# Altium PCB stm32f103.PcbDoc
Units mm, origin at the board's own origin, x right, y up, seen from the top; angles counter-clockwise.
Board outline 152.4 x 101.6 mm, 2 copper layers (Top Layer, Bottom Layer); 61 components, 40 nets, 251 pads, 92 vias.
Unrouted connection lines stored in the file: 1.
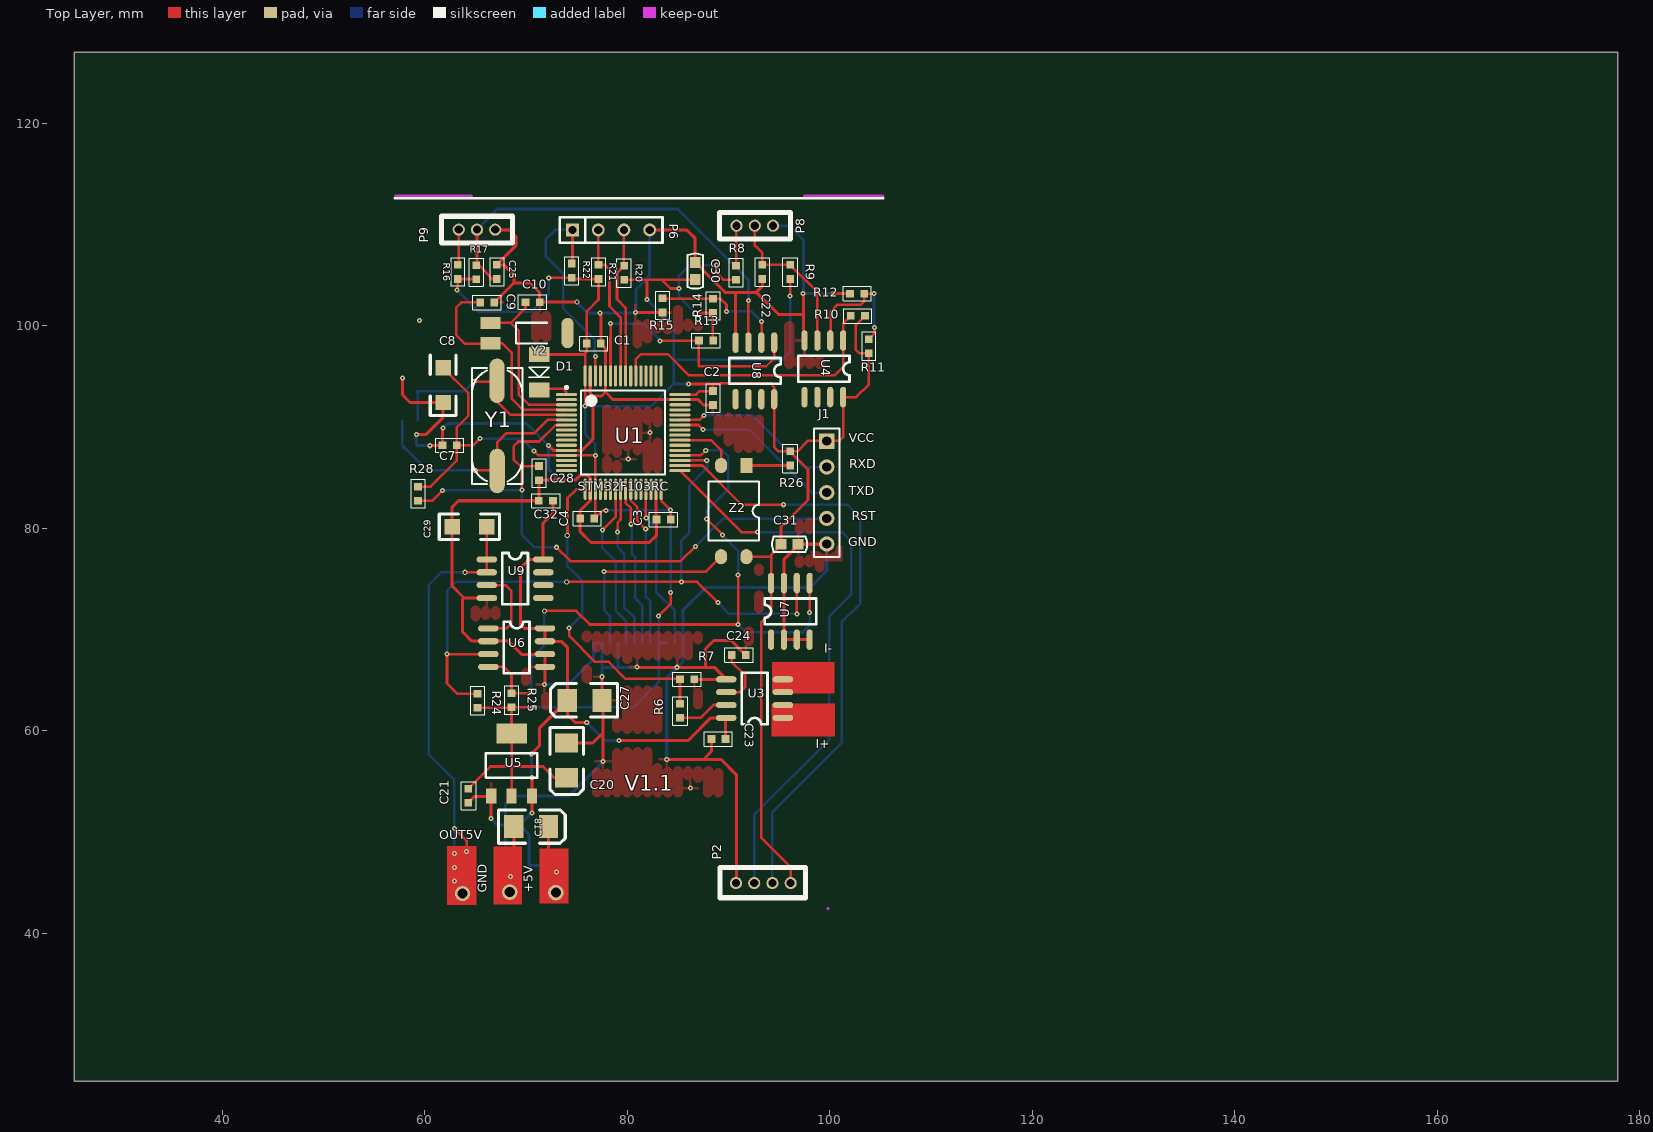
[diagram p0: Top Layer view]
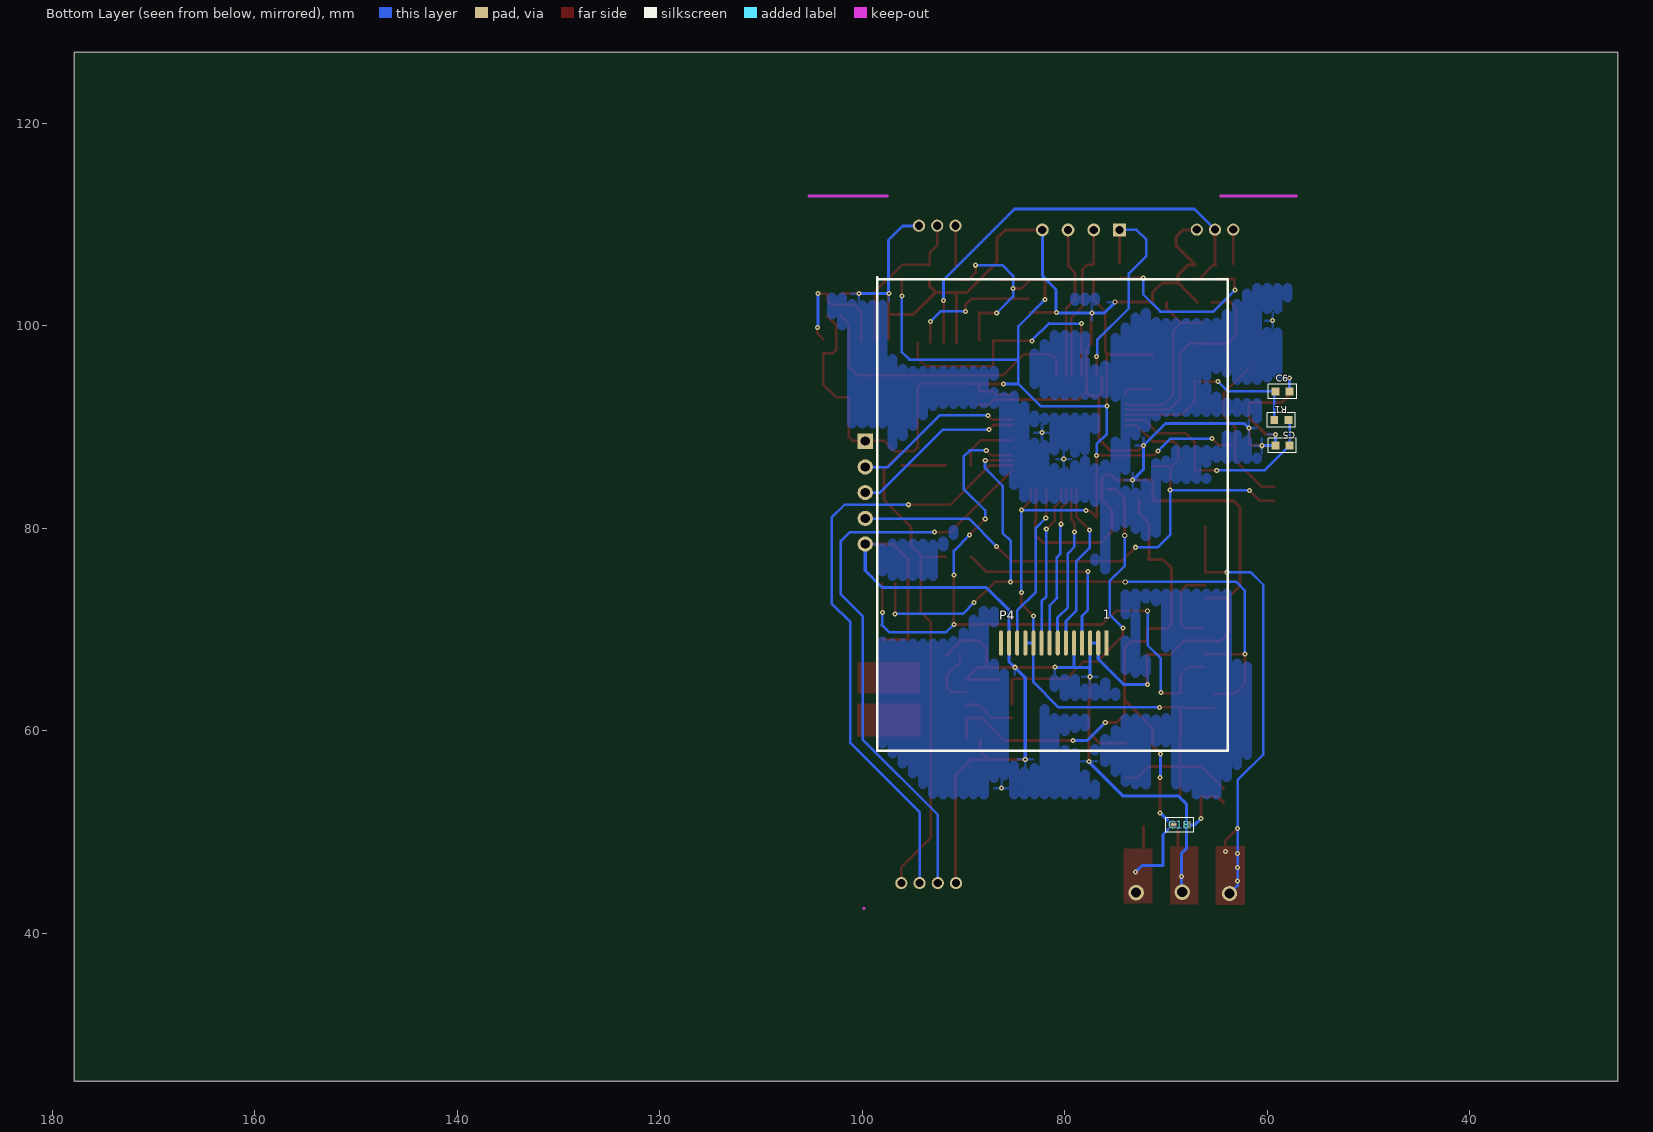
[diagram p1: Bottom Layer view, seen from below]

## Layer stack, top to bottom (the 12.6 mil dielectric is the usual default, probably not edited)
Top Layer: signal copper 0.0356
Dielectric: dielectric 0.32, FR-4, Dk 4.8
Bottom Layer: signal copper 0.0356

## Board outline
25.4,25.4 177.8,25.4 177.8,127 25.4,127

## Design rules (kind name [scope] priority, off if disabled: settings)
Clearance [All] p1: gap=0.5
PlaneClearance [All] p1: clearance=0.8
PolygonConnect [All] p1: connectstyle=Relief reliefconductorwidth=0.254 reliefentries=4 polygonreliefangle="90 Angle"
RoutingVias [All] p1: holewidth=0.2 width=0.5 viastyle="Through Hole" minholewidth=0.2 minwidth=0.5 maxholewidth=0.2 maxwidth=0.5
SMDToCorner [All] p1: distance=0
SMDToPlane [All] p1: distance=0
SilkscreenOverComponentPads [IsPad] p1: minsilkscreentomaskgap=0.254
SolderMaskExpansion [All] p1: expansion=0.5
TestPointUsage [All] p1: valid=0 allowmultiple=FALSE
Testpoint [(IsPad And (OnTopLayer Or OnBottomLayer))] p1: side=3 testpointundercomponent=TRUE minsize=1.016 maxsize=2.54 preferedsize=1.524 minholesize=0 maxholesize=1.016 preferedholesize=0.813 testpointgrid=0.025 style=297 order=0-112345678
Width GND [InNet('BOOT0')] p1: maxlimit=0.5 minlimit=0.254 preferedwidth=0.254 toplayer_minwidth=0.3 toplayer_prefwidth=0.5 bottomlayer_minwidth=0.3 bottomlayer_prefwidth=0.5 minimp=50.000000 maximp=50.000000 favimp=50.000000
Width VCC5 [InNet('VCC5')] p2: maxlimit=0.5 minlimit=0.254 preferedwidth=0.254 toplayer_minwidth=0.3 toplayer_prefwidth=0.5 bottomlayer_minwidth=0.3 bottomlayer_prefwidth=0.5 minimp=50.000000 maximp=50.000000 favimp=50.000000
Width [All] p3: maxlimit=0.3 minlimit=0.254 preferedwidth=0.254 toplayer_prefwidth=0.3 bottomlayer_prefwidth=0.3 minimp=50.000000 maximp=50.000000 favimp=50.000000
22 further rules are at their usual default settings.

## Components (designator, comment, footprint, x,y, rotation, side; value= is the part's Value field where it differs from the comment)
C1 "Cap" 0603 76,98.236 r0 top
C2 "Cap" 0603 88.462,93.563 r270 top
C3 "Cap" 0603 82.899,80.863 r0 top
C4 "Cap" 0603 75.355,80.964 r0 top
C5 "Cap" 0603 59.201,88.178 r180 bottom
C6 "Cap" 0603 57.804,93.512 r0 bottom
C7 "Cap" 0603 63.163,88.203 r180 top
C8 "Cap" 1206_C 61.817,92.42 r90 top
C9 "Cap" 0603 65.475,102.3 r0 top
C10 "Cap" 0603 69.95,102.325 r0 top
C18 "Cap" 0603 67.964,50.713 r0 bottom
C20 "10u" 3528#1 74.009,55.361 r270 top
C21 "0.1u" 0603 64.306,52.897 r90 top
C22 "104" 0603 93.338,104.612 r90 top
C23 "Cap" 0603 88.309,59.196 r0 top
C24 "Cap" 0603 91.713,67.477 r180 top
C25 "104" 0603 67.125,106.009 r270 top
C27 "10u" 3528#1 74.085,63.006 r180 top
C28 "0.1uF" 0603 72.663,82.717 r180 top
C29 "47u" 1206 66.135,80.151 r180 top
C30 "Cap" C-RAD-0603 86.709,105.399 r270 top
C31 "Cap" C-RAD-0603 96.025,78.425 r0 top
C32 "Cap" 0603 71.291,86.146 r270 top
D1 "Diode" DIODE-1206 71.304,97.16 r270 top
J1 "Header 5" HDR1X5 99.7,88.6 r270 top
P2 "霍尔接口" HEADER4---1.8 102.675,42.5 r180 top locked
P4 "1.8TFT" "1.8TFT - duplicate" 74.572,70.6 r0 bottom locked
P6 "霍尔接口" SIP4 74.593,109.463 r0 top
P8 "spead" HEADER3---1.8 95.725,108.2 r180 top locked
P9 "spead" HEADER3---1.8 68.294,107.812 r180 top
R1 "Res1" 0603 59.302,90.692 r180 bottom
R6 "Res1" 0603 85.21,61.279 r90 top
R7 "Res1" 0603 85.21,65.089 r0 top
R8 "1K" 0603 90.748,105.932 r270 top
R9 "10K" 0603 96.082,104.612 r90 top
R10 "10K" 0603 102.076,100.979 r0 top
R11 "10K" 0603 103.85,98.675 r270 top
R12 "10K" 0603 103.397,103.164 r180 top
R13 "10K" 0603 87.09,98.541 r0 top
R14 "10K" 0603 88.462,102.656 r270 top
R15 "10K" 0603 83.483,102.707 r270 top
R16 "1K" 0603 63.265,106.009 r270 top
R17 "10K" 0603 65.094,104.586 r90 top
R20 "10K" 0603 79.699,104.535 r90 top
R21 "10K" 0603 77.159,106.009 r270 top
R22 "10K" 0603 74.517,104.739 r90 top
R24 "4.7K" 0603 65.221,63.667 r270 top
R25 "4.7K" 0603 68.573,63.718 r270 top
R26 "330" 0603 96.082,86.197 r90 top
R28 "Res1" 0603 59.328,84.114 r270 top
U1 "STM32F103RC" LQFP-64 79.597,89.448 r0 top
U3 "ACS712" SO-8 95.37,61.279 r180 top
U4 "LM393" SO-8 101.314,98.541 r270 top
U5 "AMS1117-3.3" 3.3V 66.577,53.556 r90 top
U6 "MAX517" SO-8 66.287,70.118 r0 top
U7 "FM24C04A" SO-8 94.202,69.001 r90 top
U8 "LM393" SO-8 94.507,98.338 r270 top
U9 "LM358" SO-8 66.135,76.926 r0 top
Y1 "XTAL" X-SM49 67.151,90.108 r270 top
Y2 "XTAL" X-TC15 66.491,99.278 r90 top
Z2 "10u" 3528#2 72.225,50.55 r0 top (schematic designator C19)

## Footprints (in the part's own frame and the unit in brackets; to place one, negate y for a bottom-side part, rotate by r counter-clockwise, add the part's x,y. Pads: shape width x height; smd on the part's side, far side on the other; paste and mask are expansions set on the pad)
"1.8TFT - duplicate" [mm]
  rect 0.4x2.5 smd: 1(1.321,1.93)
  oval 0.4x2.5 smd: 2(2.121,1.93) 3(2.921,1.93) 4(3.721,1.93) 5(4.521,1.93) 6(5.321,1.93) 7(6.121,1.93) 8(6.921,1.93) 9(7.721,1.93) 10(8.521,1.93) 11(9.321,1.93) 12(10.121,1.93) 13(10.921,1.93) 14(11.721,1.93)
3.3V [mm]
  rect 1.5x1 smd: 1(0,0) 2(0,-2) 3(0,-4)
  rect 2x3 smd: 4(6.172,-2.007)
  silkscreen extent 1.83,-4.52 4.22,0.53
0603 [mil]
  rect 30x30 smd: 1(0,0) 2(55,0)
  silkscreen extent -28,-28 82,28
1206 [mil]
  rect 60x60 smd: 1(0,0) 2(135,0)
  silkscreen extent -50,-50 185,50
1206_C [mil]
  rect 60x60 smd: 1(0,0) 2(135,0)
  silkscreen extent -50,-50 185,50
3528#1 [mil]
  rect 75x90 smd: 1(0,0) 2(-135,0)
  silkscreen extent -195,-65 65,65
3528#2 [mil]
  rect 75x90 smd: 1(0,0) 2(-135,0)
  rect 47.24x59.06 smd: 1(769.24,1403.41)
  oval 47.24x59.06 smd: 2(670.81,1403.41) 3(670.81,1049.08) 4(769.24,1049.08)
  silkscreen extent -195,-65 818,1341
C-RAD-0603 [mm] "贴片电容"
  rect 1.1x1 smd: 1(-0.85,0) 2(0.85,0)
  silkscreen extent -1.73,-0.76 1.73,0.76, body extent -1.14,-0.38 1.14,0.38, height 1
DIODE-1206 [mm] "玻璃封装二极管"
  rect 1.5x2 smd: 1(0,0) 2(3.5,0)
  silkscreen extent 1.25,-1 2.25,1
HDR1X5 [mm] "Connector; Header; 5 Position"
  rect 1.5x1.5 hole 0.9: 1(0,0)
  round 1.5 hole 0.9: 2(2.54,0) 3(5.08,0) 4(7.62,0) 5(10.16,0)
  silkscreen extent -1.27,-1.27 11.43,1.27
HEADER3---1.8 [mm]
  round 1.2 hole 0.8: 1(1.331,-1.676) 2(3.131,-1.676) 3(4.931,-1.676)
  silkscreen extent -0.38,-3 6.63,-0.36
HEADER4---1.8 [mm]
  round 1.2 hole 0.8: 1(6.538,-2.464) 2(8.338,-2.464) 3(10.138,-2.464) 4(11.938,-2.464)
  silkscreen extent 5.05,-3.99 13.51,-1.02
LQFP-64 [mm] "LQFP64"
  oval 2.1x0.3 smd: 1(-5.6,3.75) 2(-5.6,3.25) 3(-5.6,2.75) 4(-5.6,2.25) 5(-5.6,1.75) 6(-5.6,1.25) 7(-5.6,0.75) 8(-5.6,0.25) 9(-5.6,-0.25) 10(-5.6,-0.75) 11(-5.6,-1.25) 12(-5.6,-1.75) 13(-5.6,-2.25) 14(-5.6,-2.75) 15(-5.6,-3.25) 16(-5.6,-3.75) 33(5.6,-3.75) 34(5.6,-3.25) 35(5.6,-2.75) 36(5.6,-2.25) 37(5.6,-1.75) 38(5.6,-1.25) 39(5.6,-0.75) 40(5.6,-0.25) 41(5.6,0.25) 42(5.6,0.75) 43(5.6,1.25) 44(5.6,1.75) 45(5.6,2.25) 46(5.6,2.75) 47(5.6,3.25) 48(5.6,3.75)
  oval 0.3x2.1 smd: 17(-3.75,-5.6) 18(-3.25,-5.6) 19(-2.75,-5.6) 20(-2.25,-5.6) 21(-1.75,-5.6) 22(-1.25,-5.6) 23(-0.75,-5.6) 24(-0.25,-5.6) 25(0.25,-5.6) 26(0.75,-5.6) 27(1.25,-5.6) 28(1.75,-5.6) 29(2.25,-5.6) 30(2.75,-5.6) 31(3.25,-5.6) 32(3.75,-5.6) 49(3.75,5.6) 50(3.25,5.6) 51(2.75,5.6) 52(2.25,5.6) 53(1.75,5.6) 54(1.25,5.6) 55(0.75,5.6) 56(0.25,5.6) 57(-0.25,5.6) 58(-0.75,5.6) 59(-1.25,5.6) 60(-1.75,5.6) 61(-2.25,5.6) 62(-2.75,5.6) 63(-3.25,5.6) 64(-3.75,5.6)
  silkscreen extent -5.72,-4.15 4.15,4.57, body extent -5,-5 5,5, height 1.6
SIP4 [mil]
  rect 50x50 hole 32: 1(0,0)
  round 50 hole 32: 2(100,0) 3(200,0) 4(300,0)
  silkscreen extent -50,-50 350,50
SO-8 [mil]
  oval 80x24 smd: 1(0,0) 2(0,-50) 3(0,-100) 4(0,-150) 5(220,-150) 6(220,-100) 7(220,-50) 8(220,0)
  silkscreen extent 60,-175 160,25
X-SM49 [mm]
  oval 4.4x1.5 smd: 1(4.45,0.004) 2(-4.45,-0.004)
  silkscreen extent -5.7,-2.5 5.72,2.5
X-TC15 [mm] "圆柱晶振1"
  rect 1.2x2 smd: 1(-1,0) 2(1,0)
  oval 3x1.2 smd: 3(0,-7.62)
  silkscreen extent -1.02,-5.59 1.02,-2.54, body extent -1,-8.29 1,0, height 1.99

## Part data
C1 C2 C3 C4 C5 C6 C7 C8 C9 C10 C18 C23 C24 C30 C31 C32: "无极性电容"
C20 C27 C28 C29: library part CAP
C21 C22 C25: library part Cap, "Capacitor"
D1: "二极管"
J1: "Header, 5-Pin"
P2 P6: library part "Header 4", "Header, 4-Pin"
P8 P9: library part CON3
R1 R6 R7 R28: "贴片电阻"
R8 R9 R10 R11 R12 R13 R14 R15 R16 R17 R20 R21 R22 R24 R25: library part "Res Semi", "Semiconductor Resistor"
R26: library part Res2, "Resistor"
U4 U8: library part LM358
U5: library part AMS1117
Y1 Y2: "晶振"
Z2: library part CAP+

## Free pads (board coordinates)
  round 1.5 hole 1: 2(63.725,43.925)
  round 1.524 hole 1: 3(68.4,44.075) 4(72.95,44.025)

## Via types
v1: diameter 0.5, hole 0.2, Top Layer to Bottom Layer, 87 vias
v2: diameter 0.5, hole 0.3, Top Layer to Bottom Layer, 5 vias

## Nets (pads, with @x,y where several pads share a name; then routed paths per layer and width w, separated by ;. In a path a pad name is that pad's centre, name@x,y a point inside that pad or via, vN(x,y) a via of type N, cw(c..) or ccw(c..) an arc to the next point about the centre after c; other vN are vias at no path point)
BOOT0: C1.2 C2.2 C3.1 C4.1 C5.1 C6.1 C7.2 C8.1 C9.2 C10.2 C18.1 C20.2 C21.1 C22.1 C23.1 C24.1 C25.1 C27.2 C28.2 C29.2 C30.1 C31.2 C32.2 J1.5 P2.4 P4.2 P4.3 P4.5 P4.13 P6.4 P8.1 P9.1 pad.3 R7.2 R12.2 R15.2 U1.12 U1.18 U1.28 U1.31 U1.47 U1.60 U1.63 U3.5 U4.4 U5.1 U6.2 U6.5 U6.6 U7.2 U7.3 U7.4 U7.7 U8.4 U9.4 Z2.2@68.796,50.55 | length 356.9
  Top Layer w0.3: v1@57.888,94.737 v1(57.8,94.825) 57.8,93.175 58.555,92.42 C8.1 61.817,90.967 60.1,89.25 v1@59.225,89.25 ; v1(60.527,88.152) C7.2@61.766,88.152 ; C7.2 v1@61.766,89.841 ; 63.75,72.981 63.75,69.75 64.652,68.848 U6.2 68.252,68.848 69.55,67.55 U6.6@71.847,67.55 ; C21.1 64.938,53.529 66.55,53.529 v1(66.55,51.325) ; U9.4 63.884,73.116 62.706,74.294 C29.2 62.675,80.182 62.675,82.05 63.342,82.717 C28.2 ; C9.2 68.8,104.229 68.8,105.025 67.816,106.009 C25.1 69,107.884 69,108.8 68.35,109.45 68.35,109.475 P9.1@66.976,109.475 ; 68.796,45.946 Z2.2@68.796,50.55 ; 68.804,104.225 70.4,104.225 71.347,103.278 C10.2 v2(75.025,102.325) ; C28.2@71.291,82.742 C32.2 74.874,84.749 75.373,85.248 76.054,85.248 76.347,84.955 U1.18 76.347,82.741 75.355,81.749 C4.1 75.355,79.67 76.425,78.6 82.175,78.6 82.899,79.324 C3.1 ; v1@71.875,64.625 U6.5 U6.6 ; v1(72.225,88.175) 72.702,87.698 U1.12 75.523,87.698 76.625,88.8 76.625,93.05 ; C20.2 76.59,58.79 77.6,59.8 ; U1.63 76.347,93.328 76.625,93.05 ; v1@77.397,101.203 C1.2 77.847,97.786 U1.60 77.847,93.453 77.85,93.45 ; C27.2 v1(77.514,65.339) ; v1(77.6,56.975) 77.6,59.8 ; C27.2@77.6,62.921 77.6,59.8 ; v1@80.8,101.31 R15.2 ; v1@80.975,66.275 v1(84.925,66.275) 88.597,66.275 U3.5 R7.2 ; P6.4 85.887,109.463 86.709,108.641 C30.1 89.658,103.3 92.75,103.3 ; C3.1@82.847,80.915 U1.31 ; v1(83.9,57.175) 87.525,57.175 ; U1.47 78.602,92.698 77.85,93.45 ; U1.47@85.322,92.698 87.002,92.698 87.525,92.175 C2.2@88.452,92.175 ; 87.725,66.325 87.725,68.1 88.55,68.925 90.265,68.925 C24.1 ; C23.1@88.3,59.187 88.3,57.95 87.525,57.175 ; U8.4 90.697,103.247 ; P2.4@90.775,45.002 90.775,55.675 89.275,57.175 87.525,57.175 ; C22.1 93.338,103.888 92.75,103.3 ; C31.2 J1.5@99.685,78.425 ; C31.2@96.881,78.323 95.5,76.942 95.5,76.925 95.472,76.897 U7.7 U7.2 U7.3 U7.4 ; U4.4@97.4,98.645 97.4,101.125 ; v1@97.4,103.175 97.4,101.125 ; v1(100.325,103.175) 101.989,103.175 R12.2 ; 76.625,93.05 77.45,93.05 77.85,93.45 ; 92.75,103.3 94.925,101.125 97.4,101.125
  Bottom Layer w0.3: C6.1@57.8,93.516 v1(57.8,94.825) ; v1(59.201,89.274) C5.1 v1@60.502,88.178 ; v1(61.825,89.9) 62.275,90.35 70.05,90.35 v1(72.225,88.175) 72.225,85.825 v1(73.3,84.75) ; v1(66.55,51.325) 67.162,50.713 C18.1 ; pad.3@68.475,44.15 v1(68.475,45.625) 68.475,47.9 67.964,48.411 C18.1 ; v1(71.825,64.575) 74.175,64.575 76.693,67.093 P4.2 P4.3 77.493,66.207 ; v2(75.025,102.325) 76.075,101.275 v1(77.325,101.275) v1@80.75,101.275 ; v1(77.514,65.339) 77.514,66.186 77.578,66.25 v1@80.975,66.25 ; v1@77.625,56.95 74.225,53.55 68.775,53.55 67.964,52.739 C18.1 ; 79.093,66.293 P4.5 ; v1@80.863,101.387 80.863,103.587 82.213,104.937 ; 82.213,104.938 P6.4 ; v1(83.9,57.175) 83.9,65.25 v1(84.925,66.275) ; v1@84.95,66.275 85.525,66.85 P4.13@85.525,68.638 ; P4.13 85.493,71.882 85.475,71.9 87.738,74.162 98.038,74.162 99.7,75.825 J1.5 ; P8.1@94.42,109.85 96.025,109.85 97.4,108.475 97.4,103.175 v1(100.325,103.175)
  other v1: 86.225,54.35 80.975,66.3 80.1,86.825 82.25,89.45 59.475,100.5 80.8,101.325 97.375,103.175
GO/BACK: P2.3 U1.33 | length 57.5
  Top Layer w0.254: U1.33 91.27,79.625 v1(92.85,79.625)
  Bottom Layer w0.254: P2.3 92.537,51.712 99.95,59.125 99.95,71.325 102.1,73.475 102.1,78.75 101.225,79.625 v1(92.85,79.625)
KEY+: P6.3 R20.2 U1.56 | length 15
  Top Layer w0.254: R20.2@79.673,105.958 P6.3 ; R20.2 78.991,105.224 78.991,102.625 79.847,101.769 U1.56
KEY-: P6.1 R22.2 U1.62 | length 21.8
  Top Layer w0.254: P6.1@74.517,109.387 P6.1 R22.2@74.593,106.212 ; U1.62 v1(76.847,96.972)
  Bottom Layer w0.254: P6.1 72.913,109.463 71.95,108.5 71.95,106.9 73.675,105.175 73.675,101.725 76.8,98.6 v1@76.8,97.019
KEY_MENU: P6.2 R21.1 U1.57 | length 15.7
  Top Layer w0.254: R21.1@77.133,106.034 P6.2 ; R21.1 77.816,106.009 78.25,105.575 78.25,101.925 79.347,100.828 ; U1.57 79.347,100.8
LED: U1.39 Z2.2@89.264,86.197 | length 6
  Top Layer w0.254: U1.39 88.277,88.698 89.3,87.675 Z2.2@89.3,86.233
LED_C: P4.4 Z2.3 | length 19.5
  Top Layer w0.254: v1(77.7,75.725) 87.792,75.725 Z2.3
  Bottom Layer w0.254: v1@77.735,75.725 77.735,71.89 78.3,71.325 P4.4@78.3,68.677
LM3933_1: C22.2 P8.2 R9.2 U4.3 | length 15.5
  Top Layer w0.254: P8.2 92.594,107.906 93.338,107.162 C22.2 R9.2 98.774,103.316 U4.3
LM3933_2: C25.2 P9.2 R17.2 U8.3 | length 43
  Top Layer w0.254: R17.2 65.345,105.983 66.717,104.612 ; R17.2@65.163,106.053 P9.2 ; 66.465,104.612 66.717,104.612 ; C25.2 66.717,104.612 ; U8.3 v1@91.967,102.5
  Bottom Layer w0.254: P9.2 67.2,111.525 84.975,111.525 91.975,104.525 v1(91.975,102.5)
NetC2_2: 
NetC5_2: C5.2 R1.2 U1.6 Y1.1 | length 23.1
  Top Layer w0.254: v1(64.992,85.714) 66.693,85.714 Y1.1@66.8,85.607 ; Y1.1 67.155,88.455 68.097,89.397 70.834,89.397 72.135,90.698 U1.6
  Bottom Layer w0.254: R1.2@57.804,90.591 C5.2 60.268,85.714 v1(64.992,85.714) ; C5.2@57.88,87.924 C5.2@57.905,87.949
NetC6_2: C6.2 R1.1 U1.5 Y1.2 | length 20.2
  Top Layer w0.254: v1(64.865,94.477) 66.761,94.477 Y1.2@66.791,94.507 ; Y1.2 67.147,92.503 68.429,91.221 73.974,91.221 U1.5
  Bottom Layer w0.254: C6.2 63.9,93.512 v1(64.865,94.477) ; R1.1 59.302,92.28 C6.2@59.302,93.41
NetC9_1: C9.1 U1.4 Y2.1 | length 21.9
  Top Layer w0.254: C9.1 63.625,102.3 63.1,101.775 63.1,99.075 63.95,98.225 Y2.1@66.438,98.225 ; Y2.1 67.647,98.278 68.575,97.35 68.575,92.825 69.7,91.7 U1.4@73.995,91.7 ; U1.4@73.974,91.721 U1.4@73.995,91.7 ; U1.4 U1.4@73.995,91.7
NetC10_1: C10.1 U1.3 Y2.2 | length 17.2
  Top Layer w0.254: Y2.2 68.497,100.278 ; C10.1 69.95,101.73 68.497,100.278 ; U1.3 73.995,92.2 70.275,92.2 69.3,93.175 69.3,99.475 68.497,100.278
NetC24_2: C24.2 U3.6 | length 5.8
  Top Layer w0.254: U3.6 91.144,63.819 91.625,64.3 91.625,65.5 90.316,66.809 C24.2
NetP8_3: P8.3 R8.1 | length 4
  Top Layer w0.254: R8.1 P8.3@90.748,109.895
NetP9_3: P9.3 R16.1 | length 3.4
  Top Layer w0.254: R16.1@63.363,106.107 P9.3
NetR6_1: R6.1 U3.7 | length 5.1
  Top Layer w0.254: R6.1@85.215,61.275 87.25,61.275 88.524,62.549 U3.7
NetR6_2: R6.2 R7.1 U1.17 | length 31.9
  Top Layer w0.254: v2@74.1,79.325 74.1,82.975 74.973,83.848 U1.17 ; v1(74.25,70.15) 74.275,70.125 74.275,69.35 76.825,66.8 78.175,66.8 79.85,65.125 R7.1@85.175,65.125 ; R6.2 R7.1
  Bottom Layer w0.254: v2(74.075,79.3) 74.075,76.275 75.575,74.775 75.575,71.371 ; v1(74.25,70.15) 75.471,71.371
NetR11_1: R11.1 R12.1 U4.2 | length 12.9
  Top Layer w0.254: U4.2 100.1,98.597 100.1,101.425 100.75,102.075 103.075,102.075 103.397,102.397 R12.1 v1(104.364,103.164) v1@104.375,103.175 ; R11.1 104.425,99.25 v1(104.425,99.825)
  Bottom Layer w0.254: v1@104.364,99.961 v1(104.364,103.164)
NetR14_1: R14.1 R15.1 U8.2 | length 13.1
  Top Layer w0.254: R15.1@83.534,102.656 R14.1 89.219,102.656 89.8,102.075 v1(89.8,101.425) ; U8.2@93.275,98.376 v1(93.275,100.425)
  Bottom Layer w0.254: v1(89.8,101.425) 92.275,101.425 v1(93.275,100.425)
NetR26_1: R26.1 Z2.1@91.764,86.197 | length 4.3
  Top Layer w0.254: Z2.1@91.764,86.197 R26.1
OUTPUT05V: C29.1 pad.2 U9.1 U9.2 | length 45.8
  Top Layer w0.254: v1(62.925,50.375) 64.15,49.15 64.15,47.75 ; v2(63.994,75.656) U9.2 U9.1 C29.1
  Bottom Layer w0.254: pad.2 62.925,44.725 v1(62.925,50.375) 62.925,55.125 60.4,57.65 60.4,74.425 61.631,75.656 v2(63.994,75.656)
  other v1: 62.925,45.175 62.925,46.5 62.925,47.875 64.125,48.075
OUTPUT05V_DA: U6.1 U9.3 | length 8.3
  Top Layer w0.254: U9.3 67.989,74.386 68.538,73.838 68.538,70.562 68.093,70.118 U6.1
RESET: C32.1 J1.4 R28.2 U1.7 | length 60.6
  Top Layer w0.254: R28.2 60.717,82.717 v1(61.75,83.75) ; v1(69.6,83.775) 69.6,86.125 ; C32.1@71.27,86.125 69.6,86.125 ; v1(73.025,78.125) 74.4,76.75 85.275,76.75 v1(86.725,78.2) ; U1.7 73.974,90.175 72.899,90.175 71.291,88.567 69.242,88.567 68.775,88.1 68.775,86.8 69.45,86.125 69.6,86.125
  Bottom Layer w0.254: v1(61.75,83.75) v1@69.6,83.75 ; v1(69.6,83.775) 69.6,79.35 70.825,78.125 v1(73.025,78.125) ; v1(86.725,78.2) 89.475,80.95 J1.4@99.7,80.95
REST: P4.6 U1.23 | length 16.7
  Top Layer w0.254: v1(77.55,79.825) 78.847,81.122 U1.23
  Bottom Layer w0.254: v1(77.55,79.825) 77.55,78.047 78.847,76.75 78.847,71.878 79.893,70.832
  Bottom Layer w0.3: P4.6 79.893,70.832
RXT: J1.2 U1.43 | length 17.3
  Top Layer w0.254: U1.43 87.123,90.698 v1(87.575,91.15)
  Bottom Layer w0.254: v1(87.575,91.15) 92.375,91.15 97.506,86.019 J1.2@100.196,86.019
SCL: R24.1 U1.35 U6.3 U7.6 | length 71.6
  Top Layer w0.254: v1(62.2,67.6) v1@62.2,67.578 ; R24.1 63.242,63.667 63.225,63.65 62.2,64.675 v1@62.2,67.578 ; U6.3 v1@62.2,67.578 ; v2(74.025,74.7) 86.9,74.7 v1(88.95,72.65) ; U1.35 v1@87.848,86.698 ; U7.6 96.742,71.583 v1(96.775,71.55)
  Bottom Layer w0.254: v1@62.225,67.6 62.225,73.875 63.05,74.7 v2(74.025,74.7) ; v1@85.325,74.7 85.325,78.75 86.125,79.55 86.125,84.2 87.875,85.95 v1@87.875,86.575 ; v1(88.95,72.65) 90.05,71.55 v1(96.775,71.55)
  other v1: 85.375,74.7 87.85,86.7
SDA: R25.1 U1.36 U6.4 U7.5 | length 70.4
  Top Layer w0.254: U6.4 67.817,66.308 68.573,65.552 R25.1 v1@70.443,63.718 ; v2(71.825,71.85) 74.95,71.85 76.3,70.5 v1(90.95,70.5) v1(90.95,75.375) ; U1.36 87.252,87.198 v1(87.752,87.698) ; v1(87.85,80.925) v1@89.4,79.375 ; v1(98,71.7) 98.012,71.712 U7.5
  Bottom Layer w0.254: v1(70.5,63.775) 70.5,67.125 71.825,68.45 v2(71.825,71.85) ; v1(87.752,87.698) 89.377,87.698 89.975,87.1 89.975,83.9 87.85,81.775 v1(87.85,80.925) ; v1(89.4,79.325) 90.95,77.775 v1(90.95,75.375) ; v1(90.95,70.5) 91.7,69.75 97.35,69.75 98.05,70.45 98,70.5 v1(98,71.7)
SPEED_1: R10.1 U1.54 U4.1 | length 28.9
  Top Layer w0.254: U1.54 80.847,96.697 81.35,97.2 82.925,97.2 84,97.2 86.1,95.1 100.475,95.1 101.314,95.939 U4.1 101.314,100.217 R10.1
SPEED_2: R13.1 U1.59 U8.1 | length 26.4
  Top Layer w0.254: U1.59 78.347,98.803 ; 78.35,98.806 v1(78.35,100.2) ; v1(83.225,98.5) R13.1@87.049,98.5 ; R13.1 87.05,98.501 87.05,96 93.725,96 94.507,96.782 U8.1
  Bottom Layer w0.254: v1(78.35,100.2) 81.55,100.2 ; 81.575,100.225 v1@83.225,98.575
START: P2.2 U1.34 | length 59.6
  Top Layer w0.254: U1.34 87.427,86.198 91.3,82.325 v1(95.45,82.325)
  Bottom Layer w0.254: P2.2 94.337,51.962 101.175,58.8 101.175,70.725 103.025,72.575 103.025,81.05 101.75,82.325 v1(95.45,82.325)
TFT_A0: P4.7 U1.24 | length 15.9
  Top Layer w0.254: v1@79.063,79.638 79.063,80.563 79.347,80.847 U1.24
  Bottom Layer w0.254: v1(79.05,79.625) 79.05,78.175 79.7,77.525 79.7,72.2 80.675,71.225
  Bottom Layer w0.3: P4.7 80.693,71.207
TFT_CS: P4.12 U1.29 | length 16.3
  Top Layer w0.254: v1@81.847,81.028 U1.29
  Bottom Layer w0.254: v1(81.875,81) 82.85,80.025 82.85,73.725 84.693,71.882 P4.12
TFT_SCK: P4.9 U1.26 | length 16
  Top Layer w0.254: U1.26 80.347,82.753 80.975,82.125 80.975,80.775 v1(81.825,79.925)
  Bottom Layer w0.254: v1(81.825,79.925) 81.825,73.275 82.275,72.825 P4.9@82.275,68.688
TFT_SDA: P4.8 U1.25 | length 15.8
  Top Layer w0.254: U1.25 79.847,82.503 80.35,82 v1(80.35,80.4)
  Bottom Layer w0.254: v1(80.35,80.4) 80.454,80.296 80.454,77.446 80.775,77.125 80.775,73.15 ; 80.75,73.125 81.475,72.4 P4.8@81.475,68.688
"TX D": D1.2 U1.1 | length 3
  Top Layer w0.254: D1.2@71.419,93.775 73.7,93.775 73.997,93.478 U1.1
TXD: J1.3 U1.42 | length 17.2
  Top Layer w0.254: U1.42 87.027,90.198 v1(87.475,89.75)
  Bottom Layer w0.254: v1(87.475,89.75) 92.025,89.75 98.287,83.488 ; 98.32,83.52 J1.3
VCC3.3: C1.1 C2.1 C3.2 C4.2 C7.1 C8.2 C20.1 C21.2 C30.2 C31.1 D1.1 J1.1 P2.1 P4.10 P4.11 R8.2 R9.1 R10.2 R11.2 R13.2 R14.2 R16.2 R17.1 R20.1 R21.2 R22.1 R24.2 R25.2 R26.2 R28.1 U1.13 U1.19 U1.32 U1.48 U1.64 U4.8 U5.2 U5.4 U7.8 U8.8 Z2.4 | length 303.6
  Top Layer w0.254: R28.1 60.589,84.114 63.163,86.688 C7.1 ; C8.2 64.3,93.366 64.3,91.1 63.163,89.963 C7.1 ; v1@63.265,103.525 R16.2 R17.1@65.068,104.612 ; C21.2 66.487,56.475 68.584,56.475 ; R24.2 R25.2@68.523,62.27 ; v1(65.475,88.85) 64.828,88.203 C7.1 ; U5.4@68.573,59.738 R25.2 v1(70.646,62.321) ; U5.2@68.584,53.563 68.584,56.475 ; U5.4 68.584,56.475 ; v1(70.775,87.65) 71.225,87.2 72.571,87.2 72.573,87.198 U1.13 v1@76.846,87.198 ; D1.1 75.837,97.16 ; v1@72.289,104.739 R22.1 ; C20.1 72.814,55.361 71.7,56.475 68.584,56.475 ; R22.1@74.644,104.612 R21.2 77.159,102.575 76,101.416 C1.1 76,97.459 75.847,97.306 U1.64 v1(75.847,92.053) ; v1@76.847,87.197 U1.19 76.847,81.059 77.538,81.75 v1(77.9,81.75) ; R20.1@79.712,104.549 83.4,104.549 ; v1(81.95,102.575) 81.95,104.524 ; v1(83.093,71.343) 84.275,72.525 v1(84.275,73.675) ; U1.32 83.347,82.753 v1(84.275,81.825) ; C3.2 v1@84.296,81.804 ; v1(85.1,103.675) 84.274,103.675 83.4,104.549 ; U1.48 86.798,93.198 87.15,93.55 C2.1@88.449,93.55 ; v1(86.05,94.25) 89.149,94.25 89.224,94.325 94.125,94.325 94.507,93.943 U8.8@94.507,92.825 ; C30.2 83.4,104.549 ; v1(86.716,101.259) R14.2 R13.2@88.462,98.566 ; C2.1 88.462,94.188 ; v1(88.8,105.975) 88.8,105.25 89.525,104.525 R8.2@90.737,104.525 ; Z2.4 94.13,77.197 ; U8.8 94.507,88.018 94.925,87.6 R26.2@96.075,87.6 ; v1(96.082,102.932) R9.1 ; P2.1 96.137,46.538 93.225,49.45 93.225,70.7 94.202,71.677 U7.8 94.202,77.344 95.175,78.317 95.175,78.45 95.181,78.456 95.181,80.131 97.85,82.8 97.85,85.825 R26.2 96.794,87.594 97.85,88.65 100.975,88.65 101.314,88.989 U4.8 U4.8@101.336,92.975 ; U4.8@101.317,92.95 102.6,92.95 103.85,94.2 R11.2 102.922,97.278 102.575,97.625 102.575,100.081 R10.2
  Bottom Layer w0.254: v1(63.2,103.525) 65.325,101.4 70.55,101.4 72.25,103.1 v1(72.25,104.7) ; v1(65.475,88.85) 69.575,88.85 v1(70.775,87.65) ; v1(70.646,62.321) 80.596,62.321 83.093,64.818 P4.10 ; v1(76.85,87.2) 76.85,88.325 75.847,89.328 v1(75.847,92.053) 82.378,92.053 84.575,94.25 ; v1(77.9,81.75) 77.925,81.775 v1@84.225,81.775 ; v1(81.95,102.575) 84.575,99.95 84.575,94.25 ; v1(83.093,71.343) P4.10 ; P4.11 P4.10 ; v1(84.275,73.675) v1(84.275,81.825) ; 84.675,96.65 95.35,96.65 96.082,97.382 v1(96.082,102.932) ; v1(86.05,94.25) 84.575,94.25 ; v1(86.716,101.259) 85.1,102.875 v1(85.1,103.675) 85.1,104.925 86.15,105.975 v1(88.8,105.975)
VCC5: C18.2 C23.2 C27.1 C28.1 pad.4 U3.8 U5.3 U6.7 U6.8 U9.8 Z2.1@72.225,50.55 | length 75.4
  Top Layer w0.3: v1(70.55,57.725) 71.325,58.5 71.325,60.246 C27.1 ; v1(70.575,51.9) U5.3@70.575,53.554 ; U5.3 v1@70.577,55.36 ; U9.8@71.7,76.949 71.7,80.525 72.663,81.488 C28.1 ; U9.8@71.766,76.968 U9.8 70.301,76.926 69.475,76.1 69.475,70.475 69.85,70.1 69.868,70.118 U6.8 U6.7 ; U6.7@71.924,68.8 73.525,68.8 74.085,68.24 C27.1 ; Z2.1@72.225,50.55 72.225,48.15 73,47.375 v1(73,46.075) pad.4@73,44.075 ; v1(76,60.825) 74.875,60.825 74.085,61.615 C27.1 ; v1(79.175,59.05) 86.025,59.05 88.254,61.279 U3.8 ; C23.2 U3.8@89.706,61.203
  Bottom Layer w0.3: v1@70.55,55.4 v1(70.55,57.725) ; v1(70.575,51.9) 69.388,50.713 C18.2 70.301,49.773 70.301,46.7 72.375,46.7 v1(73,46.075) ; v1(76,60.825) 77.775,59.05 v1(79.175,59.05)
  other v1: 70.577,55.373
pads on no net: P4.1 P4.14 U1.2 U1.8 U1.9 U1.10 U1.11 U1.14 U1.15 U1.16 U1.20 U1.21 U1.22 U1.27 U1.30 U1.37 U1.38 U1.40 U1.41 U1.44 U1.45 U1.46 U1.49 U1.50 U1.51 U1.52 U1.53 U1.55 U1.58 U1.61 U3.1 U3.2 U3.3 U3.4 U4.5 U4.6 U4.7 U7.1 U8.5 U8.6 U8.7 U9.5 U9.6 U9.7 Y2.3
copper on no net: | length 2.5
  Top Layer w0.3: 95.37,61.279 95.37,62.549 ; 95.37,63.819 95.37,65.089

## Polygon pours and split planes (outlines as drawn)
BOOT0 on Top Layer "Top Overlay-No Net" (hatched Vertical grid 1 track 1, remove dead copper, pour order 1000): 63,54.052 63.125,53.925 99.05,53.925 99.05,102.407 98.774,102.688 98.149,103.325 62.5,103.325 62.5,54.816 62.875,54.434
BOOT0 on Top Layer "Bottom Layer-No Net" (solid, pour order 76): 98.1,79.725 98.125,79.7 101.225,79.7 101.225,76.775 101.2,76.75 98.1,76.75 98.1,79.725
BOOT0 on Bottom Layer "Top Overlay-No Net" (hatched Vertical grid 1 track 1, remove dead copper, pour order 1004): 57.462,103.339 58.5,102.279 58.5,73.425 72.069,73.425 72.212,73.571 72.55,73.916 72.55,103.289 57.849,103.289 57.559,103.585
BOOT0 on Bottom Layer "Top Overlay-No Net" (hatched Vertical grid 1 track 1, remove dead copper, pour order 1003): 104.975,103.85 101.45,100.325 101.45,54.825 94.575,54.825 94.45,54.7 92.025,57.125 92.025,89.75 92.025,90.9 104.975,103.85
BOOT0 on Bottom Layer "Top Overlay-No Net" (hatched Vertical grid 1 track 1, remove dead copper, pour order 1002): 57.3,103.75 59.787,101.224 59.787,60.625 70.473,60.625 83.425,73.783 65.376,92.118 65.376,103.675
BOOT0 on Bottom Layer "Top Overlay-No Net" (hatched Vertical grid 1 track 1, remove dead copper, pour order 1001): 61.717,53.475 61.717,99.641 58.725,102.774 104.602,102.774 104.65,102.825 101.44,99.464 101.44,53.728 61.959,53.728 61.717,53.475

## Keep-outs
Keep-Out Layer:
  lines w0.254: 99.818,42.483 99.845,42.456
  lines w0.3: 57.134,112.82 64.634,112.82 ; 97.509,112.82 105.259,112.82

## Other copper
Top Layer:
  rectangle: 94.25,59.425 100.5,62.7
  rectangle: 94.275,63.675 100.45,66.775
  rectangle net OUTPUT05V: 62.225,42.8 65.125,48.65
  rectangle net BOOT0: 66.8,42.875 69.625,48.575
  rectangle net VCC5: 71.325,42.95 74.175,48.375

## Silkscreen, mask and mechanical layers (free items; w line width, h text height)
Top Overlay:
  lines w0.254: 57.046,112.584 105.262,112.584 105.263,112.583
  text "VCC" at 101.85,88.175 h1.52
  text "RXD" at 101.925,85.625 h1.52
  text "STM32F103RC" at 75.125,83.4 h1.52
  text "TXD" at 101.875,82.95 h1.52
  text "RST" at 102.15,80.5 h1.52
  text "GND" at 101.8,77.925 h1.52
  text "I-" at 99.475,67.4 h1.52
  text "I+" at 98.6,58 h1.52
  text "V1.1" at 79.75,54.1 h1.52
  text "OUT5V" at 61.425,48.975 h1.52
  text "GND" at 66.425,44.025 h1.52 r90
  text "+5V" at 70.95,44.025 h1.52 r90
Bottom Overlay:
  lines w0.254: 98.499,58.027 63.904,58.027 63.904,104.611 98.499,104.611 ; 98.499,58.177 98.499,104.761
  text "1" at 76.223,70.779 h1.52
Top Solder:
  rectangle: 94.175,63.675 100.45,66.825
  rectangle: 94.2,59.4 100.25,62.65
  rectangle: 62.25,42.775 65.125,48.65
  rectangle: 66.85,42.875 69.6,48.55
  rectangle: 71.375,42.975 74.175,48.4
Mechanical 1:
  circle w0.254: c97.257,49.645 r1.75
  circle w0.254: c101.016,105.856 r1.75
  circle w0.254: c59.525,105.9 r1.75
  lines w0.254: 57.062,112.825 ccw(c279.523,93.061) 61.992,42.467 ; 57.148,112.739 57.174,112.765 ; 99.881,42.456 ccw(c-125.215,95.119) 105.295,112.632 105.295,112.853
  lines w0.3: 61.992,42.467 74.867,42.467 74.975,42.575 74.975,52.769 ; 64.688,112.82 97.538,112.82 ; 74.975,52.912 87.8,52.912 ; 87.8,42.483 99.854,42.483 99.881,42.456 ; 87.85,42.625 87.85,52.944 ; 105.295,112.632 105.295,112.853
